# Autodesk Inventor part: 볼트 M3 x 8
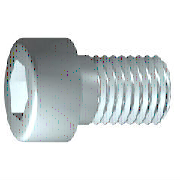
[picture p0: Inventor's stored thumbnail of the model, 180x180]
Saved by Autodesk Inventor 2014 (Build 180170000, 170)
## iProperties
Created: 2012-02
Part Number: 볼트 M3 x 8
Material: 스테인리스강
Description: 6각 소켓 머리 캡 나사
Document SubType Name: Modeling
Standard: ISO 4762
Designer: mduedu
Standard Revision: Fourth edition 2004-03-01
Standards Organization: ISO
Language: ko-KR
Size Designation: M3 x 8
Categories: <MemberInstance><Categories><Category DisplayName="조임쇠" InternalName="e4da775c-781d-43d5-af7c-5136215cf5a6" Mnemonic="FSTN"><Category DisplayName="볼트" InternalN
Density: 8.08 g/cm^3
Appearance: 반광택
IsCustomPart: 0
Author: mduedu
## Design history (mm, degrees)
sketch "스케치1"
  geometry: L1 (-0.867, 0)-(8, 0); L2 (8, 0)-(8, 1.5); L3 (8, 1.5)-(1.25, 1.5); L4 (1.25, 1.5)-(0.943, 1.5); L5 (0.943, 1.5)-(0, 1.5); L6 (0, 1.5)-(0, 2.75); L7 (0, 2.75)-(-3, 2.75); L8 (-3, 2.75)-(-3, 1.443); L9 (-3, 1.443)-(-1.7, 1.443); L10 (-1.7, 1.443)-(-0.867, 0); L11 (-5.2, 0)-(10.2, 0) reference; L12 (0, -0.55)-(0, 3.3) reference; L13 (1.25, 1.5)-(0, 1.5)
  constraints: 22 end point, 6 parallel, 2 collinear, 2 perpendicular, 1 horizontal, 1 point on line
  dimensions: "d1" = 6.75 distance from line of L3.end L2 (= GEL); "d2" = 0.30683 distance of L4.end L3.end (computed from GAL); "d3" = 3 distance between parallel lines of L8 L6 (= KOH); "d4" = 1.3 distance of L8.end L9.end (= INTI); "d5" = 60 deg angle of L10 L1; "d6" = 3 diameter of L3 L1 (= GD); "d7" = 3 diameter of L5 L1 (= BDM); "d8" = 2.88675 diameter of L9 L1 (= 1.1547 x SW); "d9" = 5.5 diameter of L7 L1 (= KOD); "d26" = 8 distance between parallel lines of L12 L2 (= NLG)
revolve "본체" sketch "스케치1" stored, may be unused: angle "d10" = 90 deg
sketch "스케치2"
  geometry: L1 (0, -3.85)-(0, 3.85) reference; L2 (-3.85, 0)-(3.85, 0) reference; L3 (1.443, 0)-(0.722, -1.25); L4 (0.722, -1.25)-(-0.722, -1.25); L5 (-0.722, -1.25)-(-1.443, 0); L6 (-1.443, 0)-(-0.722, 1.25); L7 (-0.722, 1.25)-(0.722, 1.25); L8 (0.722, 1.25)-(1.443, 0); 2 further points
  constraints: 12 end point, 1 coincident, 1 horizontal alignment, 1 point on line, 12 other
extrude "슬롯" join sketch "스케치2" stored distance "d11" = 10; taper "d12" = 0 deg
workplane "Work Plane1"
fillet "Fillet2" dims "d30" = 0.1 (= R)
body "Solid1"
fillet "모깎기1" dims "d17" = 0.3 (= RR)
feature "스레드" dims "d13" = 6.75 (= GEL), "d14" = 0
chamfer "모따기1" distance "d15" = 0.30673 (= -0.5 x SPD + 0.5 x GD); stored, may be unused: second distance "d16" = 0.30673 (= GUL), angle "d27" = 45 deg
other parameters: "GD" = 3 [user parameter; used in 2 equation terms], "NLG" = 8 [user parameter; used in 1 equation term], "GEL" = 6.75 [user parameter; used in 2 equation terms], "KOD" = 5.5 [user parameter; used in 1 equation term], "KOH" = 3 [user parameter; used in 1 equation term], "INTI" = 1.3 [user parameter; used in 1 equation term], "GAL" = 0.30673 (= 0.61345 x PTC) [user parameter; used in 1 equation term], "GUL" = 0.30673 (= 0.61345 x PTC) [user parameter; used in 1 equation term], "BDM" = 3 (= NND) [user parameter; used in 1 equation term], "SW" = 2.5 [user parameter; used in 2 equation terms], "RR" = 0.3 [user parameter; used in 1 equation term], "SPD" = 2.38655 (= NND - 1.2269 x PTC) [user parameter; used in 1 equation term], "d19" = 0, "d28" = 0, "d29" = 0, "R" = 0.1 [user parameter; used in 1 equation term], "TOA" = 30 deg [user parameter], "GD1" = 2.38655 (= THREADDIA - 1.2269 x PTC) [user parameter], "THREADDIA" = 3 [user parameter; used in 1 equation term], "FAWI" = 45 deg [user parameter], "PTC" = 0.5 [user parameter; used in 5 equation terms], "NND" = 3 [user parameter; used in 2 equation terms], "E0" = 2.8875 (= 1.155 x SW) [user parameter]
